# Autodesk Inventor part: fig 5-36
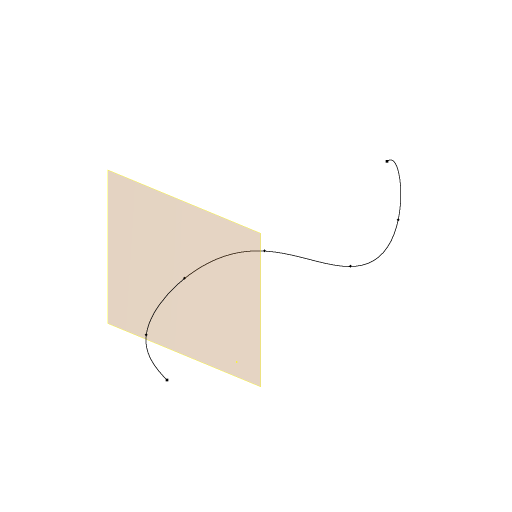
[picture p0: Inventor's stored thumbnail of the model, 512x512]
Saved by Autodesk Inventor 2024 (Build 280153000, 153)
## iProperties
Created: 2010-02
Part Number: fig 5-36
Document SubType Name: Modeling
Designer: CADSoft
Density: 1 g/cm^3
Material: Generic
Appearance: Default
Author: CADSoft
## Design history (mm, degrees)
sketch "Sketch1"
  geometry: 8 further points
  constraints: 8 other
workplane "Work Plane1"
workplane "Work Plane2"
